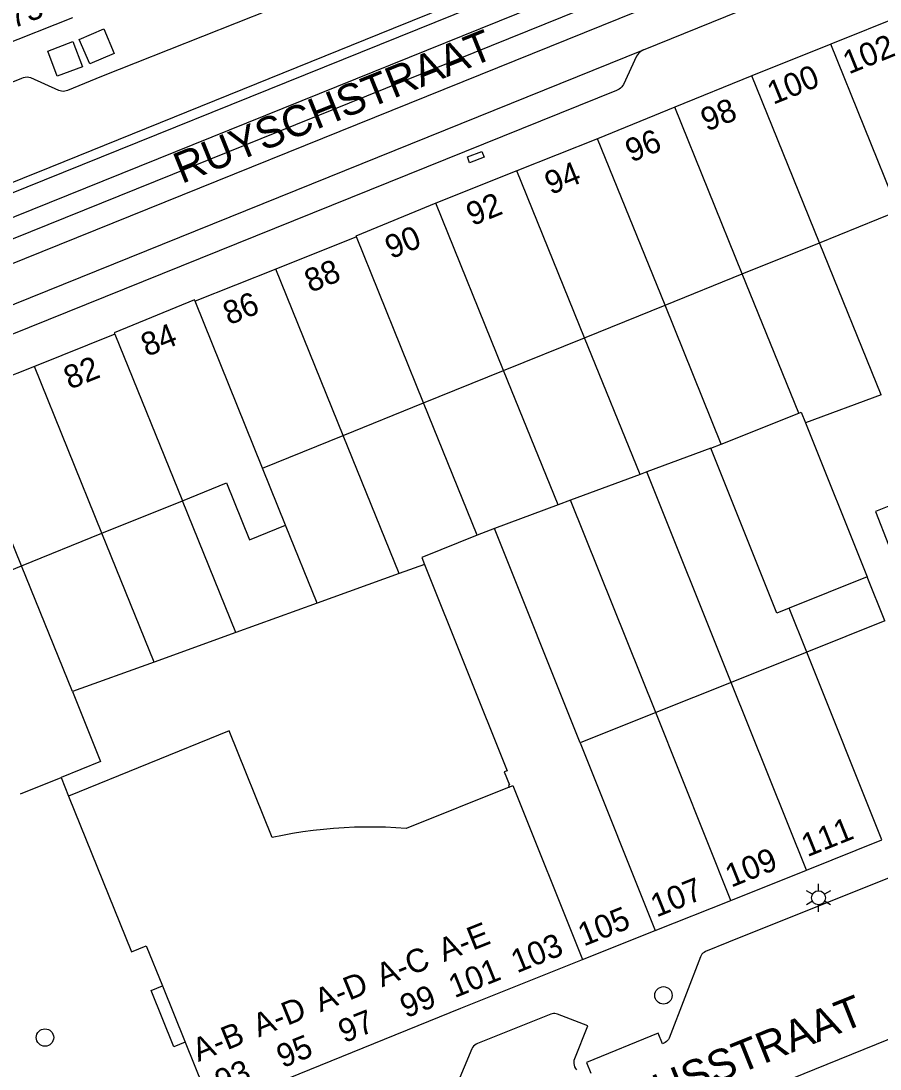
# Model space of a CAD drawing. Extents: x 122462 to 123306, y 485548 to 486417.
# Drawn here: x 122612.1 to 122667.6, y 485605.8 to 485673.5 of the extents above; entities that cross this region are included whole.
import ezdxf

# ---------------------------------------------------------------- set-up
doc = ezdxf.new("R2010")
doc.units = 0
for name, color, linetype in [('Level 1', 7, 'Continuous'), ('Level 17', 7, 'Continuous'), ('Level 19', 7, 'Continuous'), ('Level 2', 7, 'Continuous'), ('Level 22', 7, 'Continuous'), ('Level 23', 7, 'Continuous'), ('Level 37', 7, 'Continuous'), ('Level 4', 7, 'Continuous'), ('Level 40', 7, 'Continuous'), ('Level 42', 7, 'Continuous'), ('Level 50', 7, 'Continuous'), ('Level 53', 7, 'Continuous'), ('Level 58', 7, 'Continuous'), ('Level 59', 7, 'Continuous')]:
    doc.layers.add(name, color=color, linetype=linetype)

msp = doc.modelspace()

# ---------------------------------------------------------------- linework, layer by layer
at = {"layer": 'Level 1'}
for p, q in [((122615.462, 485673.664), (122610.778, 485671.823)), ((122669.39, 485673.989), (122664.385, 485671.963)), ((122664.385, 485671.963), (122659.299, 485669.929)), ((122659.299, 485669.929), (122654.32, 485667.9)), ((122654.32, 485667.9), (122649.35, 485665.85)), ((122649.35, 485665.85), (122644.14, 485663.799)), ((122644.14, 485663.799), (122638.91, 485661.699)), ((122663.665, 485659.157), (122668.74, 485661.212)), ((122633.782, 485659.528), (122628.581, 485657.451)), ((122658.681, 485657.138), (122663.665, 485659.157)), ((122628.581, 485657.451), (122623.376, 485655.373)), ((122653.698, 485655.119), (122658.681, 485657.138)), ((122648.509, 485653.018), (122653.698, 485655.119)), ((122618.199, 485653.259), (122613.009, 485651.17)), ((122643.285, 485650.902), (122648.509, 485653.018)), ((122613.009, 485651.17), (122607.799, 485649.09)), ((122638.123, 485648.811), (122643.285, 485650.902)), ((122632.932, 485646.708), (122638.123, 485648.811)), ((122627.733, 485644.602), (122632.932, 485646.708)), ((122629.219, 485640.934), (122627.733, 485644.602)), ((122617.372, 485640.406), (122622.558, 485642.507)), ((122612.172, 485638.3), (122617.372, 485640.406)), ((122642.687, 485640.716), (122641.581, 485640.273)), ((122648.224, 485626.878), (122642.687, 485640.716)), ((122667.884, 485634.745), (122662.842, 485632.728)), ((122662.842, 485632.728), (122657.969, 485630.778)), ((122657.969, 485630.778), (122653.093, 485628.826)), ((122653.093, 485628.826), (122648.224, 485626.878)), ((122662.818, 485618.661), (122667.689, 485620.61)), ((122657.939, 485616.709), (122662.818, 485618.661)), ((122653.07, 485614.759), (122657.939, 485616.709)), ((122648.382, 485612.889), (122653.07, 485614.759)), ((122621.274, 485611.192), (122622.737, 485607.562))]:
    msp.add_line(p, q, dxfattribs=at)
for points in [[(122638.91, 485661.699), (122633.759, 485659.579), (122633.782, 485659.528)], [(122623.376, 485655.373), (122623.34, 485655.459), (122618.165, 485653.35), (122618.199, 485653.259)], [(122622.558, 485642.507), (122625.403, 485643.659), (122626.889, 485639.99), (122629.219, 485640.934)], [(122641.581, 485640.273), (122637.998, 485638.839), (122638.175, 485638.396)], [(122609.038, 485631.188), (122611.309, 485632.107), (122609.276, 485637.127), (122612.172, 485638.3)], [(122638.175, 485638.396), (122643.503, 485625.08), (122643.328, 485625.009), (122643.666, 485624.164), (122643.591, 485624.134), (122643.636, 485624.022)], [(122643.636, 485624.022), (122636.995, 485621.344), (122636.328, 485621.392), (122635.66, 485621.425), (122634.991, 485621.442), (122634.323, 485621.444), (122633.654, 485621.43), (122632.986, 485621.4), (122632.318, 485621.355), (122631.652, 485621.295), (122630.988, 485621.219), (122630.325, 485621.128), (122629.665, 485621.021), (122629.008, 485620.899), (122628.353, 485620.762), (122625.579, 485627.643), (122615.219, 485623.431)], [(122615.219, 485623.431), (122619.269, 485613.393), (122620.23, 485613.78), (122621.274, 485611.192)], [(122622.737, 485607.562), (122624.485, 485603.227), (122640.519, 485609.749), (122648.382, 485612.889)]]:
    msp.add_lwpolyline(points, dxfattribs=at)
at = {"layer": 'Level 17'}
for p, q in [((122652.311, 485671.603), (122660.23, 485674.806)), ((122597.556, 485649.471), (122652.311, 485671.603))]:
    msp.add_line(p, q, dxfattribs=at)
for points in [[(122709.48, 485702.109), (122709.528, 485702.192), (122709.561, 485702.281), (122709.581, 485702.375), (122709.585, 485702.47), (122709.574, 485702.565), (122709.548, 485702.657), (122709.508, 485702.744), (122709.454, 485702.823), (122709.389, 485702.893), (122709.313, 485702.952), (122709.23, 485702.998), (122709.14, 485703.03), (122709.046, 485703.047), (122708.95, 485703.049), (122704.34, 485700.629), (122693.14, 485695.979), (122669.178, 485686.34), (122636.16, 485672.989), (122614.01, 485664.019), (122548.688, 485637.731), (122544.761, 485636.151)], [(122544.301, 485640.741), (122545.656, 485642.934), (122545.716, 485643.021), (122545.785, 485643.101), (122545.862, 485643.173), (122545.947, 485643.237), (122546.037, 485643.291), (122546.133, 485643.336), (122612.195, 485669.786), (122612.305, 485669.824), (122612.419, 485669.846), (122612.536, 485669.852), (122612.651, 485669.842), (122612.765, 485669.817), (122614.576, 485669), (122614.671, 485668.969), (122614.769, 485668.952), (122614.869, 485668.947), (122614.969, 485668.955), (122615.066, 485668.976), (122615.16, 485669.01), (122617.368, 485669.906), (122628.222, 485674.197)], [(122652.311, 485671.603), (122652.219, 485671.555), (122652.132, 485671.498), (122652.052, 485671.431), (122651.98, 485671.357), (122651.916, 485671.274), (122651.861, 485671.186), (122651.011, 485669.376), (122650.96, 485669.288), (122650.899, 485669.207), (122650.828, 485669.134), (122650.748, 485669.07), (122650.661, 485669.018), (122650.568, 485668.976), (122600.403, 485648.744)], [(122668.587, 485618.34), (122657.798, 485614.02), (122656.308, 485613.4), (122656.222, 485613.355), (122656.144, 485613.297), (122656.077, 485613.228), (122656.021, 485613.148), (122655.979, 485613.061)], [(122633.077, 485593.54), (122692.946, 485617.824)], [(122655.979, 485613.061), (122653.963, 485607.821), (122653.913, 485607.739), (122653.853, 485607.663), (122653.785, 485607.595), (122653.71, 485607.535), (122653.628, 485607.485), (122653.541, 485607.444), (122653.261, 485608.132), (122648.629, 485606.251), (122648.9, 485605.549)], [(122647.996, 485605.777), (122647.933, 485605.868), (122647.883, 485605.967), (122647.849, 485606.073), (122647.83, 485606.182), (122647.826, 485606.293), (122647.839, 485606.404), (122647.867, 485606.511), (122648.725, 485608.607), (122646.759, 485609.368), (122646.676, 485609.392), (122646.59, 485609.404), (122646.503, 485609.405), (122646.417, 485609.395), (122646.333, 485609.373), (122641.602, 485607.481), (122641.508, 485607.435), (122641.421, 485607.375), (122641.344, 485607.304), (122641.279, 485607.221), (122641.227, 485607.13), (122638.968, 485601.721)]]:
    msp.add_lwpolyline(points, dxfattribs=at)
at = {"layer": 'Level 19'}
for p, q in [((122667.645, 485649.332), (122663.665, 485659.157)), ((122662.318, 485648.16), (122658.681, 485657.138)), ((122657.326, 485646.162), (122653.698, 485655.119)), ((122652.082, 485644.198), (122648.509, 485653.018)), ((122646.795, 485642.239), (122643.285, 485650.902)), ((122667.645, 485649.332), (122662.764, 485647.539)), ((122641.581, 485640.273), (122638.123, 485648.811)), ((122636.538, 485637.804), (122632.932, 485646.708)), ((122656.644, 485645.889), (122652.532, 485644.365)), ((122652.532, 485644.365), (122652.082, 485644.198)), ((122657.969, 485630.778), (122652.532, 485644.365)), ((122652.082, 485644.198), (122647.606, 485642.539)), ((122626.005, 485633.995), (122622.558, 485642.507)), ((122647.606, 485642.539), (122646.795, 485642.239)), ((122653.093, 485628.826), (122647.606, 485642.539)), ((122646.795, 485642.239), (122642.687, 485640.716)), ((122631.26, 485635.895), (122629.219, 485640.934)), ((122620.741, 485632.091), (122617.372, 485640.406)), ((122615.46, 485630.181), (122612.172, 485638.3)), ((122638.175, 485638.396), (122636.538, 485637.804)), ((122636.538, 485637.804), (122631.26, 485635.895)), ((122667.884, 485634.745), (122666.746, 485637.588)), ((122631.26, 485635.895), (122626.005, 485633.995)), ((122662.842, 485632.728), (122661.704, 485635.571)), ((122626.005, 485633.995), (122620.741, 485632.091)), ((122620.741, 485632.091), (122615.46, 485630.181))]:
    msp.add_line(p, q, dxfattribs=at)
for points in [[(122675.803, 485662.392), (122676.141, 485661.543), (122676.442, 485661.663), (122682.099, 485647.412), (122669.514, 485642.417), (122669.416, 485642.664), (122667.268, 485641.812), (122668.122, 485639.66), (122668.91, 485639.973), (122670.094, 485636.991), (122669.52, 485636.763), (122670.367, 485634.635)], [(122615.46, 485630.181), (122617.285, 485625.676), (122614.731, 485624.642)]]:
    msp.add_lwpolyline(points, dxfattribs=at)
at = {"layer": 'Level 2'}
for p, q in [((122657.326, 485646.162), (122662.318, 485648.16)), ((122662.764, 485647.539), (122666.746, 485637.588)), ((122656.644, 485645.889), (122657.326, 485646.162)), ((122666.746, 485637.588), (122661.704, 485635.571))]:
    msp.add_line(p, q, dxfattribs=at)
for points in [[(122662.318, 485648.16), (122662.488, 485648.228), (122662.764, 485647.539)], [(122661.704, 485635.571), (122660.901, 485635.249), (122656.644, 485645.889)]]:
    msp.add_lwpolyline(points, dxfattribs=at)
at = {"layer": 'Level 22'}
msp.add_lwpolyline([(122622.737, 485607.562), (122622.008, 485607.268), (122620.545, 485610.898), (122621.274, 485611.192)], dxfattribs=at)
at = {"layer": 'Level 23'}
for p, q in [((122612.118, 485623.583), (122614.731, 485624.642)), ((122614.731, 485624.642), (122615.219, 485623.431))]:
    msp.add_line(p, q, dxfattribs=at)
at = {"layer": 'Level 37'}
for points in [[(122831.695, 485753.286), (122749.349, 485719.414), (122746.888, 485718.394), (122744.433, 485717.362), (122741.982, 485716.318), (122739.537, 485715.262), (122737.097, 485714.193), (122734.663, 485713.112), (122732.234, 485712.019), (122729.811, 485710.913), (122727.393, 485709.796), (122725.051, 485708.714), (122722.702, 485707.646), (122720.348, 485706.592), (122717.987, 485705.55), (122715.621, 485704.523), (122713.249, 485703.509), (122710.871, 485702.509), (122708.487, 485701.522), (122706.098, 485700.549), (122540.465, 485633.647), (122497.591, 485615.701), (122462.03, 485601.437)], [(122832.259, 485751.918), (122749.912, 485718.045), (122747.458, 485717.028), (122745.009, 485715.999), (122742.566, 485714.958), (122740.128, 485713.905), (122737.695, 485712.839), (122735.267, 485711.761), (122732.845, 485710.671), (122730.428, 485709.568), (122728.017, 485708.454), (122725.667, 485707.369), (122723.311, 485706.297), (122720.949, 485705.239), (122718.581, 485704.195), (122716.207, 485703.164), (122713.827, 485702.146), (122711.441, 485701.143), (122709.049, 485700.153), (122706.652, 485699.177), (122541.028, 485632.278), (122498.152, 485614.332), (122462.03, 485599.841)], [(122462.03, 485598.45), (122499.057, 485613.321), (122548.623, 485633.976), (122706.621, 485697.803), (122708.996, 485698.77), (122711.365, 485699.751), (122713.729, 485700.746), (122716.087, 485701.753), (122718.44, 485702.774), (122720.787, 485703.808), (122723.127, 485704.856), (122725.462, 485705.916), (122727.791, 485706.99), (122730.21, 485708.107), (122732.634, 485709.211), (122735.064, 485710.304), (122737.499, 485711.384), (122739.94, 485712.452), (122742.386, 485713.508), (122744.837, 485714.552), (122747.294, 485715.584), (122749.755, 485716.603), (122832.9, 485750.796)], [(122833.463, 485749.428), (122750.317, 485715.234), (122747.862, 485714.217), (122745.413, 485713.189), (122742.969, 485712.148), (122740.53, 485711.095), (122738.096, 485710.029), (122735.667, 485708.952), (122733.244, 485707.863), (122730.827, 485706.761), (122728.414, 485705.648), (122726.078, 485704.571), (122723.735, 485703.506), (122721.387, 485702.455), (122719.033, 485701.418), (122716.672, 485700.394), (122714.306, 485699.383), (122711.935, 485698.385), (122709.557, 485697.401), (122707.175, 485696.431), (122549.185, 485632.607), (122499.617, 485611.951), (122462.03, 485596.856)]]:
    msp.add_lwpolyline(points, dxfattribs=at)
at = {"layer": 'Level 4'}
for p, q in [((122668.74, 485661.212), (122664.385, 485671.963)), ((122663.665, 485659.157), (122659.299, 485669.929)), ((122658.681, 485657.138), (122654.32, 485667.9)), ((122653.698, 485655.119), (122649.35, 485665.85)), ((122648.509, 485653.018), (122644.14, 485663.799)), ((122643.285, 485650.902), (122638.91, 485661.699)), ((122638.123, 485648.811), (122633.782, 485659.528)), ((122632.932, 485646.708), (122628.581, 485657.451)), ((122627.733, 485644.602), (122623.376, 485655.373)), ((122618.199, 485653.259), (122622.558, 485642.507)), ((122617.372, 485640.406), (122613.009, 485651.17)), ((122612.172, 485638.3), (122607.799, 485649.09)), ((122667.689, 485620.61), (122662.842, 485632.728)), ((122662.818, 485618.661), (122657.969, 485630.778)), ((122657.939, 485616.709), (122653.093, 485628.826)), ((122648.224, 485626.878), (122653.07, 485614.759))]:
    msp.add_line(p, q, dxfattribs=at)
msp.add_lwpolyline([(122643.636, 485624.022), (122643.886, 485624.123), (122648.382, 485612.889)], dxfattribs=at)
at = {"layer": 'Level 40'}
msp.add_lwpolyline([(122641.092, 485664.315), (122640.95, 485664.688), (122641.884, 485665.045), (122642.026, 485664.672), (122641.092, 485664.315)], dxfattribs=at)
at = {"layer": 'Level 42'}
for points in [[(122616.578, 485670.694), (122615.902, 485672.279), (122617.487, 485672.955), (122618.163, 485671.37), (122616.578, 485670.694)], [(122614.481, 485669.895), (122613.868, 485671.525), (122615.498, 485672.138), (122616.111, 485670.508), (122614.481, 485669.895)]]:
    msp.add_lwpolyline(points, dxfattribs=at)
at = {"layer": 'Level 50'}
for p, q in [((122663.207, 485617.105), (122662.817, 485617.33)), ((122663.597, 485617.33), (122663.597, 485617.78)), ((122664.376, 485617.33), (122663.986, 485617.105)), ((122663.207, 485616.655), (122662.817, 485616.43)), ((122664.376, 485616.43), (122663.986, 485616.655)), ((122663.597, 485615.98), (122663.597, 485616.43))]:
    msp.add_line(p, q, dxfattribs=at)
msp.add_circle((122663.597, 485616.88), 0.45, dxfattribs=at)
at = {"layer": 'Level 53'}
for centre in [(122653.597, 485610.581), (122613.695, 485607.859)]:
    msp.add_circle(centre, 0.56, dxfattribs=at)

# ---------------------------------------------------------------- texts
at = {"layer": 'Level 58'}
for s, rotation, p in [('73', 21.45719, (122611.638, 485672.967)), ('102', 22.02048, (122665.555, 485670.01)), ('100', 22.02048, (122660.675, 485668.05)), ('98', 22.02048, (122656.388, 485666.317)), ('96', 22.02048, (122651.52, 485664.321)), ('94', 22.02048, (122646.318, 485662.227)), ('92', 22.02048, (122641.259, 485660.215)), ('90', 22.02048, (122636.017, 485658.085)), ('88', 22.02048, (122630.821, 485655.916)), ('86', 22.02048, (122625.568, 485653.818)), ('84', 22.02048, (122620.267, 485651.781)), ('82', 22.02048, (122615.29, 485649.665)), ('111', 21.88252, (122662.874, 485619.489)), ('109', 21.88252, (122657.963, 485617.523)), ('107', 21.88252, (122653.145, 485615.596)), ('105', 21.77791, (122648.459, 485613.726)), ('A-E', 21.76118, (122639.432, 485612.718)), ('103', 22.01439, (122644.143, 485611.996)), ('A-C', 22.13819, (122635.44, 485611.096)), ('101', 22.01439, (122640.117, 485610.388)), ('A-D', 22.13819, (122631.464, 485609.479)), ('99', 22.01439, (122636.987, 485609.093)), ('A-D', 22.13819, (122627.477, 485607.857)), ('97', 22.01439, (122633.004, 485607.482)), ('A-B', 22.13819, (122623.582, 485606.272)), ('95', 22.01439, (122629.021, 485605.871)), ('93', 22.01439, (122625.038, 485604.26))]:
    msp.add_text(s, height=1.5, rotation=rotation, dxfattribs=at).set_placement(p)
at = {"layer": 'Level 59'}
for s, rotation, p in [('RUYSCHSTRAAT', 21.95782, (122622.518, 485662.944)), ('BLASIUSSTRAAT', 21.91205, (122646.409, 485600.648))]:
    msp.add_text(s, height=2, rotation=rotation, dxfattribs=at).set_placement(p)

doc.saveas('drawing.dxf')
